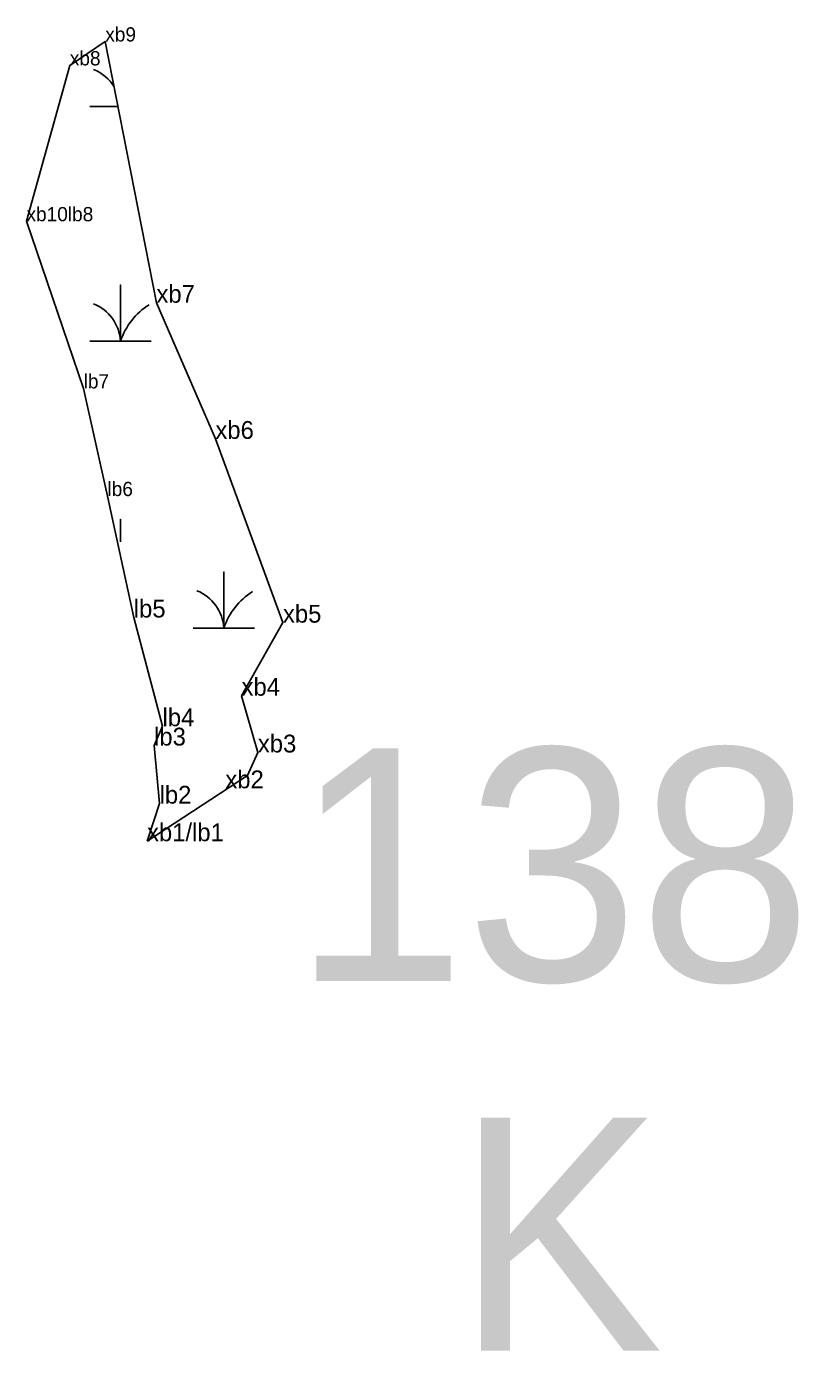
# Model space of a CAD drawing. Extents: x 2072529 to 2268796, y 436423 to 470406.
# Drawn here: x 2163568.5 to 2163785.1, y 440216.7 to 440588.3 of the extents above; entities that cross this region are included whole.
import ezdxf

# ---------------------------------------------------------------- set-up
doc = ezdxf.new("R2010")
doc.units = 0
for name, color, linetype in [('Default', 7, 'Continuous'), ('Exist Environmental Wetland Boundary Cogo Comment', 7, 'Continuous'), ('Exist Environmental Wetland Boundary Cogo Point CELL', 7, 'Continuous'), ('Old_Level_20', 7, 'Continuous')]:
    doc.layers.add(name, color=color, linetype=linetype)

msp = doc.modelspace()

# ---------------------------------------------------------------- linework, layer by layer
at = {"layer": 'Exist Environmental Wetland Boundary Cogo Comment'}
for p, q in [((2163590.57, 440584.09), (2163590.57, 440584.09)), ((2163580.62, 440577.38), (2163580.62, 440577.38)), ((2163568.46, 440533.63), (2163568.46, 440533.63)), ((2163604.94, 440510.75), (2163604.94, 440510.75)), ((2163584.5, 440486.71), (2163584.5, 440486.71)), ((2163591.19, 440456.5), (2163591.19, 440456.5))]:
    msp.add_line(p, q, dxfattribs=at)
at = {"layer": 'Exist Environmental Wetland Boundary Cogo Point CELL'}
for points in [[(2163586.27, 440565.8), (2163594.15, 440565.8)], [(2163586.27, 440500), (2163594.87, 440500), (2163594.87, 440515.78), (2163594.87, 440500), (2163603.47, 440500)], [(2163594.87, 440443.7), (2163594.87, 440449.98), (2163594.87, 440443.7)], [(2163615.26, 440419.45), (2163623.87, 440419.45), (2163623.87, 440435.23), (2163623.87, 440419.45), (2163632.47, 440419.45)]]:
    msp.add_lwpolyline(points, dxfattribs=at)
for centre, radius, start, end in [((2163582.6, 440564.91), 12.3, 31.7302, 67.535), ((2163582.6, 440499.11), 12.3, 4.1403, 67.535), ((2163613.11, 440493.94), 19.22, 122.1274, 161.6222), ((2163611.6, 440418.57), 12.3, 4.1403, 67.535), ((2163642.11, 440413.39), 19.22, 122.1274, 161.6222)]:
    msp.add_arc(centre, radius, start, end, dxfattribs=at)
at = {"layer": 'Old_Level_20'}
for p, q in [((2163604.94, 440510.75), (2163604.94, 440510.75)), ((2163604.94, 440510.75), (2163604.94, 440510.75)), ((2163604.94, 440510.75), (2163604.94, 440510.75)), ((2163621.48, 440472.55), (2163621.48, 440472.55)), ((2163598.57, 440422.41), (2163598.57, 440422.41)), ((2163640.44, 440420.97), (2163640.44, 440420.97)), ((2163628.82, 440400.46), (2163628.82, 440400.46)), ((2163606.64, 440391.89), (2163606.64, 440391.89)), ((2163604.27, 440386.48), (2163604.27, 440386.48)), ((2163633.4, 440384.53), (2163633.4, 440384.53)), ((2163624.27, 440374.48), (2163624.27, 440374.48)), ((2163605.81, 440370.17), (2163605.81, 440370.17)), ((2163602.29, 440359.62), (2163602.29, 440359.62))]:
    msp.add_line(p, q, dxfattribs=at)
msp.add_lwpolyline([(2163602.29, 440359.62), (2163605.81, 440370.17), (2163604.27, 440386.48), (2163606.64, 440391.89), (2163598.57, 440422.41), (2163591.19, 440456.5), (2163584.5, 440486.71), (2163568.46, 440533.63), (2163580.62, 440577.38), (2163590.57, 440584.09), (2163604.94, 440510.75), (2163621.48, 440472.55), (2163640.44, 440420.97), (2163628.82, 440400.46), (2163633.4, 440384.53), (2163630.49, 440378.09)], close=True, dxfattribs=at)

# ---------------------------------------------------------------- texts
at = {"layer": 'Default'}
for s, p in [('138', (2163643.14, 440320.37)), ('K', (2163688.81, 440216.67))]:
    msp.add_text(s, height=65.34, dxfattribs=at).set_placement(p)
at = {"layer": 'Exist Environmental Wetland Boundary Cogo Comment'}
for s, height, p in [('xb9', 4, (2163590.57, 440584.09)), ('xb8', 4, (2163580.62, 440577.38)), ('xb10lb8', 4, (2163568.46, 440533.63)), ('xb7', 5, (2163604.94, 440510.75)), ('lb7', 4, (2163584.5, 440486.71)), ('xb6', 5, (2163621.48, 440472.55)), ('lb6', 4, (2163591.19, 440456.5)), ('lb5', 5, (2163598.57, 440422.41)), ('xb5', 5, (2163640.44, 440420.97)), ('xb4', 5, (2163628.82, 440400.46)), ('lb4', 5, (2163606.64, 440391.89)), ('lb3', 5, (2163604.27, 440386.48)), ('xb3', 5, (2163633.4, 440384.53)), ('xb2', 5, (2163624.27, 440374.48)), ('lb2', 5, (2163605.81, 440370.17)), ('xb1/lb1', 5, (2163602.29, 440359.62))]:
    msp.add_text(s, height=height, dxfattribs=at).set_placement(p)

doc.saveas('drawing.dxf')
